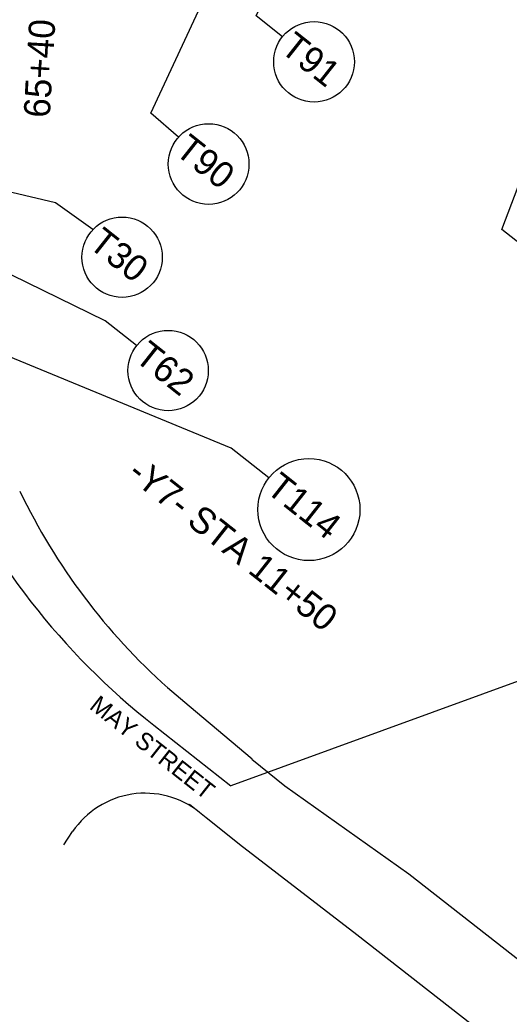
# Model space of a CAD drawing. Extents: x 553958 to 562499, y 493978 to 516388.
# Drawn here: x 557807.8 to 557919.7, y 506659.2 to 506886.7 of the extents above; entities that cross this region are included whole.
import ezdxf

# ---------------------------------------------------------------- set-up
doc = ezdxf.new("R2010")
doc.units = 0
for name, color, linetype in [('Prop Approach Slab', 7, 'Continuous'), ('Prop Horizontal Alignment Tick Label', 7, 'Continuous'), ('Prop SS Fill Line', 7, 'Continuous'), ('Prop Superelevation Label', 7, 'Continuous'), ('Raster_Level_0', 7, 'Continuous'), ('Scratch_Level_0', 7, 'Continuous'), ('Sheet Plan CELL', 7, 'Continuous')]:
    doc.layers.add(name, color=color, linetype=linetype)

msp = doc.modelspace()

# ---------------------------------------------------------------- linework, layer by layer
at = {"layer": 'Prop Approach Slab'}
msp.add_lwpolyline([(558014.97, 506678.87), (557936.61, 506740.83), (557856.04, 506711.44)], dxfattribs=at)
at = {"layer": 'Prop Horizontal Alignment Tick Label'}
msp.add_line((557817.78, 506697.95), (557818.63, 506699.2), dxfattribs=at)
at = {"layer": 'Prop SS Fill Line'}
for p, q in [((557841.56, 506733.91), (557846.47, 506729.72)), ((557846.47, 506729.72), (557860.9, 506717.62)), ((557846.54, 506707.23), (557850.35, 506704.21)), ((557817.78, 506697.95), (557819.83, 506700.98))]:
    msp.add_line(p, q, dxfattribs=at)
for centre, radius, start, end in [((557937.48, 506841.2), 143.93, 205.681, 228.2181), ((557836.39, 506689.75), 20, 51.5968, 145.8636)]:
    msp.add_arc(centre, radius, start, end, dxfattribs=at)
at = {"layer": 'Raster_Level_0'}
msp.add_line((557838.43, 506725.29), (557856.04, 506711.44), dxfattribs=at)
msp.add_arc((557940.45, 506854.97), 165, 204.0535, 231.806, dxfattribs=at)
at = {"layer": 'Scratch_Level_0'}
for points in [[(557942.77, 506661.5), (557928.53, 506667.97), (557926.47, 506667.94), (557896.75, 506691.22), (557868.37, 506711.35), (557860.8, 506717.49)], [(557914.23, 506652.41), (557913.42, 506655.03), (557884.82, 506677.31), (557858, 506698.04), (557850.33, 506704.19)]]:
    msp.add_lwpolyline(points, dxfattribs=at)
at = {"layer": 'Sheet Plan CELL'}
for points in [[(557844.07, 506859.85), (557837.72, 506865.32), (557861.6, 506916.67)], [(557867.83, 506882.81), (557861.78, 506887.6), (557873.72, 506913.27)], [(557923.32, 506834.56), (557918.03, 506838.74), (557933.38, 506879.1)], [(557824.48, 506838.7), (557815.88, 506844.83), (557754.27, 506859.43)], [(557834.46, 506812.15), (557827.3, 506817.81), (557770.47, 506845.56)], [(557864.74, 506781.88), (557856.09, 506788.72), (557789.06, 506816.34)]]:
    msp.add_lwpolyline(points, dxfattribs=at)
for centre, radius in [((557875.06, 506877.09), 9.22), ((557850.94, 506853.7), 9.22), ((557831.15, 506832.38), 9.19), ((557841.68, 506806.44), 9.19), ((557873.89, 506774.64), 11.67)]:
    msp.add_circle(centre, radius, dxfattribs=at)

# ---------------------------------------------------------------- texts
at = {"layer": 'Prop Superelevation Label'}
msp.add_text('MAY STREET', height=4, rotation=321.6667, dxfattribs=at).set_placement((557823.45, 506729.25))
at = {"layer": 'Sheet Plan CELL'}
for s, rotation, p in [(' 65+40', 86.6749, (557814.46, 506861.95)), ('T91', 321.6667, (557867.06, 506879.59)), ('T90', 321.6667, (557842.94, 506856.2)), ('T30', 321.6667, (557823.18, 506834.86)), ('T62', 321.6667, (557833.7, 506808.92)), ('-Y7- STA 11+50', 321.6667, (557832.05, 506782.23)), ('T114', 321.6667, (557863.76, 506778.83))]:
    msp.add_text(s, height=6, rotation=rotation, dxfattribs=at).set_placement(p)

doc.saveas('drawing.dxf')
